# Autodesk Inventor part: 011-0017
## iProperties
Created: 2007-02
Part Number: 011-0017
Document SubType Name: Modeling
Designer: GG5883
Description: Axe serrage
Stock Number: 11-0017
Material: 34 Cr Mo 4
Checked By: GG5883
Author: GG5883
Revision Number: 00
Title: AXE DE SERRAGE
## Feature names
1. Volume base [Revolution]
2. Centrage came [Revolution]
3. centrage sur support de mors [Revolution]
4. rainure d'arrêt [Revolution]
5. chanfrein d'entrée [Chamfer]
6. chanfrein tête de came [Chamfer]
